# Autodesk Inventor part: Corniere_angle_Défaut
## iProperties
Created: 2011-01
Part Number: Corniere_angle_Défaut
Document SubType Name: Modeling
Designer: eric
Density: 1 g/cm^3
Mass: 1.71774 g
Surface Area: 25.4242 cm^2
Volume: 1.71774 cm^3
Author: eric
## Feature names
1. Base1
